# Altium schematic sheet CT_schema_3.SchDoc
size 321 x 302 mm
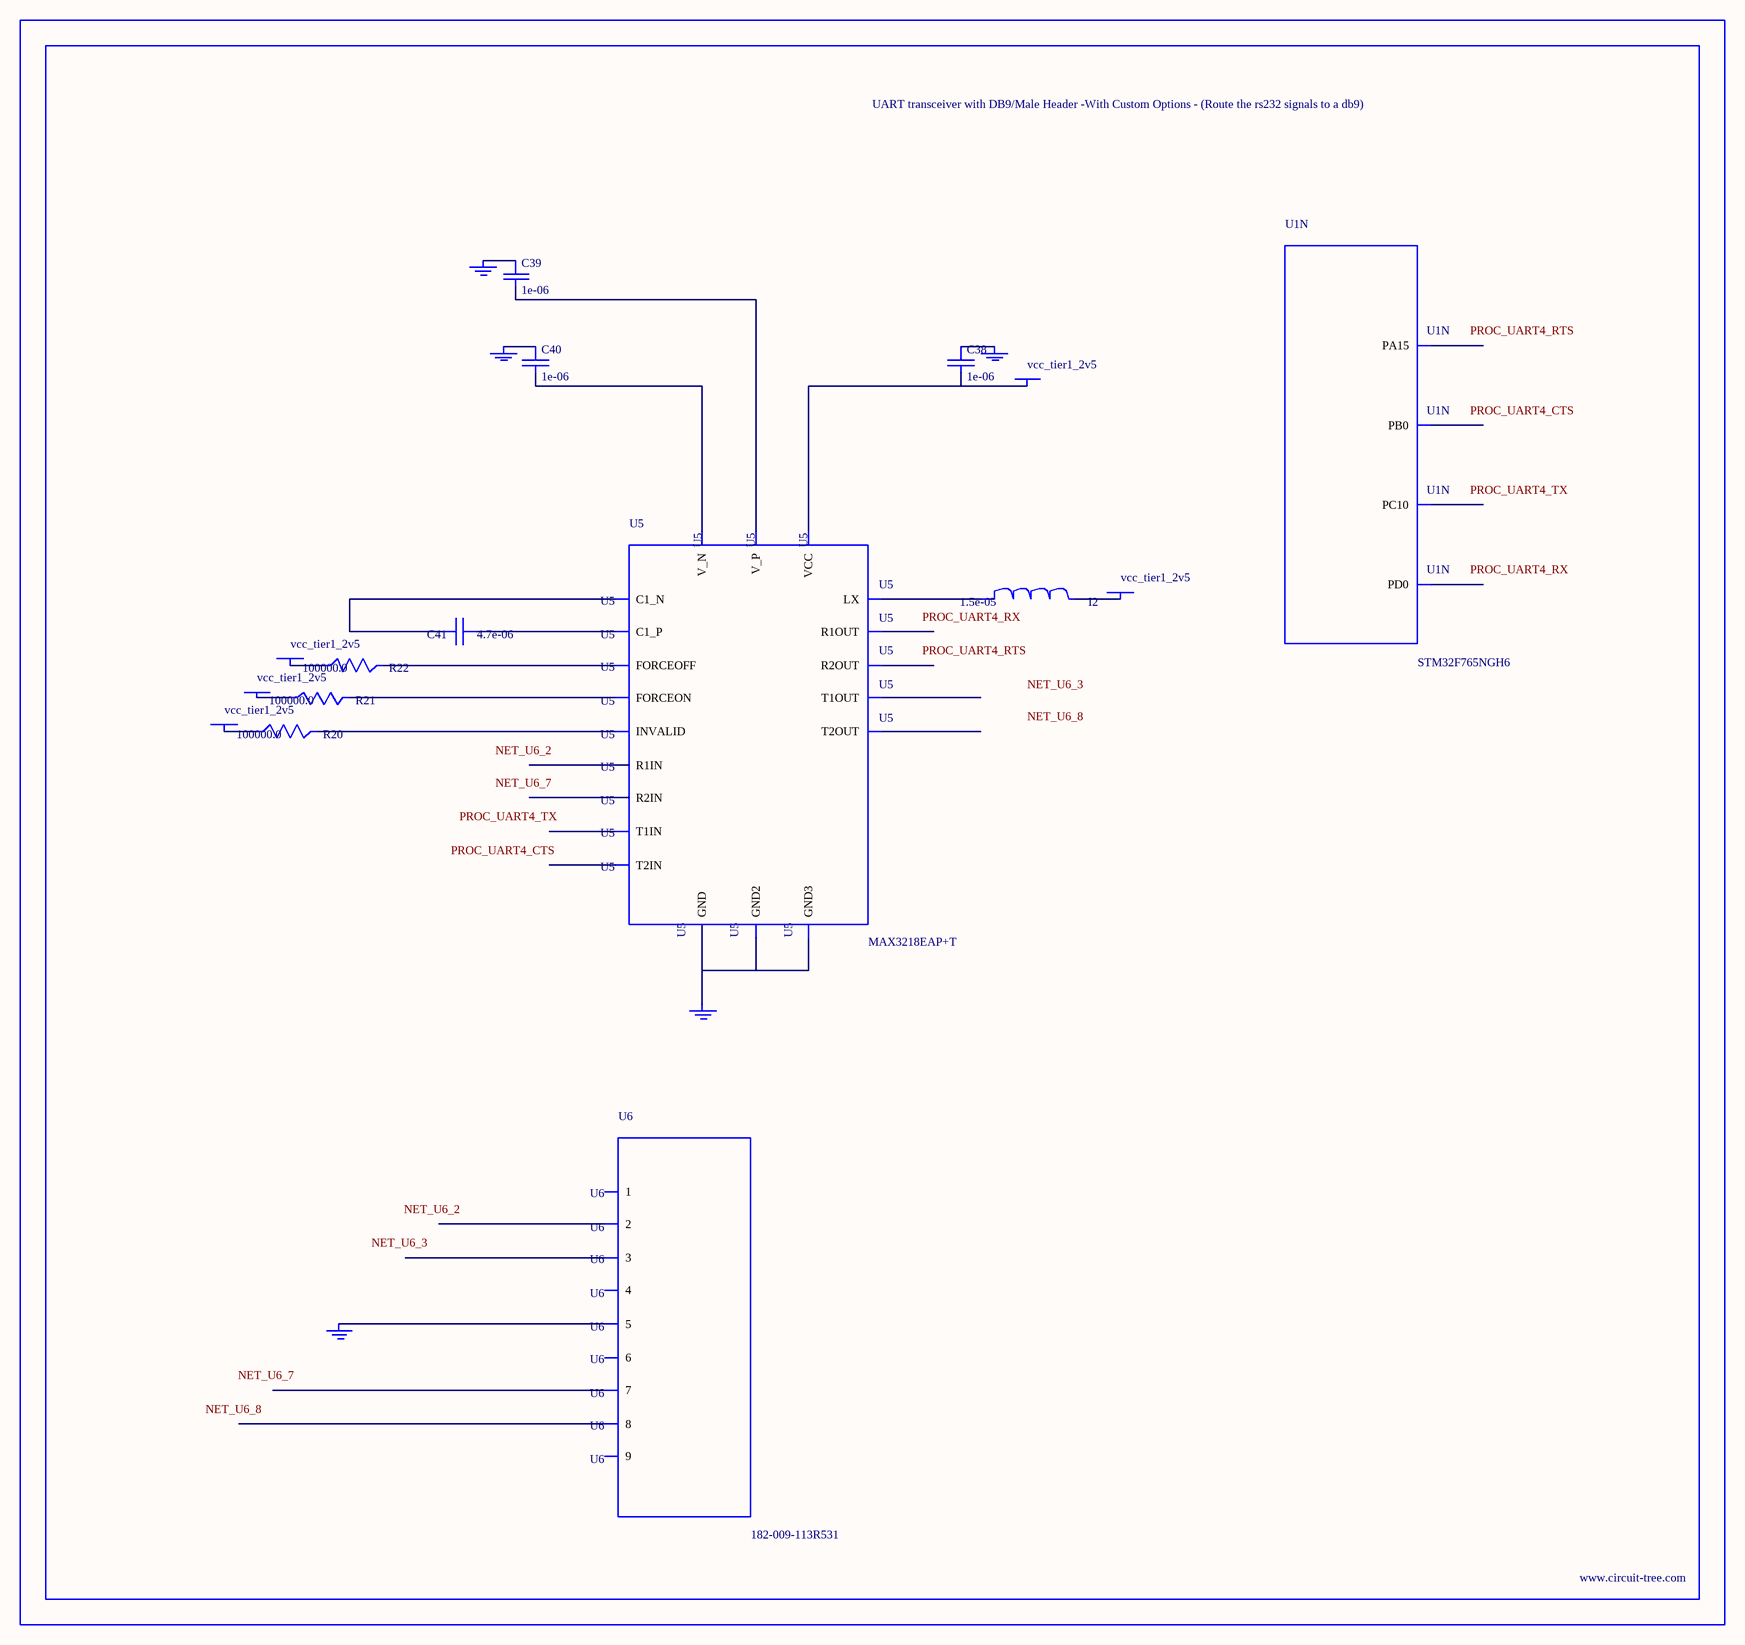
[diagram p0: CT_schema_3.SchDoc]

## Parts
BORDER2  (no value)
C38  1e-06  [C0603]
C39  1e-06  [C0603]
C40  1e-06  [C0603]
C41  4.7e-06  [C0805]
GND_INSTANCE_2_0  (no value)
GND_INSTANCE_2_1  (no value)
GND_INSTANCE_2_2  (no value)
GND_INSTANCE_2_3  (no value)
GND_INSTANCE_2_4  (no value)
I2  1.5e-05  [L1210]
POWER_INSTANCE_2_0  vcc_tier1_2v5
POWER_INSTANCE_2_1  vcc_tier1_2v5
POWER_INSTANCE_2_2  vcc_tier1_2v5
POWER_INSTANCE_2_3  vcc_tier1_2v5
POWER_INSTANCE_2_4  vcc_tier1_2v5
R20  100000.0  [R0603]
R21  100000.0  [R0603]
R22  100000.0  [R0603]
U1  STM32F765NGH6  [TFBGA216]  (part N of 18)
U5  MAX3218EAP+T  [SSOP-20]
U6  182-009-113R531  [182-009-MALE]

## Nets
NetC38_1: C38.1 GND_INSTANCE_2_0.0(GND)
NetC38_2: C38.2 POWER_INSTANCE_2_4.0(PWR) U5.6(VCC)
NetC39_1: C39.1 GND_INSTANCE_2_2.0(GND)
NetC39_2: C39.2 U5.19(V_P)
NetC40_1: C40.1 GND_INSTANCE_2_1.0(GND)
NetC40_2: C40.2 U5.15(V_N)
NetC41_1: C41.1 U5.18(C1_P)
NetC41_2: C41.2 U5.16(C1_N)
NetGND_INSTANCE_2_3_0: GND_INSTANCE_2_3.0(GND) U5.5(GND) U5.17(GND2) U5.20(GND3)
NetGND_INSTANCE_2_4_0: GND_INSTANCE_2_4.0(GND) U6.5
NetI2_1: I2.1 U5.1(LX)
NetI2_2: I2.2 POWER_INSTANCE_2_0.0(PWR)
NetPOWER_INSTANCE_2_1_0: POWER_INSTANCE_2_1.0(PWR) R20.1
NetPOWER_INSTANCE_2_2_0: POWER_INSTANCE_2_2.0(PWR) R21.1
NetPOWER_INSTANCE_2_3_0: POWER_INSTANCE_2_3.0(PWR) R22.1
NetR20_2: R20.2 U5.2(INVALID)
NetR21_2: R21.2 U5.3(FORCEON)
NetR22_2: R22.2 U5.4(FORCEOFF)

Not connected (* = marked no-connect by the designer): U1 A13(PA15) B12(PD0) B14(PC10) R5(PB0); U5 7(T1IN) 8(T2IN) 9(R1OUT) 10(R2OUT) 11(R2IN) 12(R1IN) 13(T2OUT) 14(T1OUT); U6 1 2 3 4 6 7 8 9

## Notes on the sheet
- Labels drawn without touching a wire or pin: NET_U6_2, NET_U6_3, NET_U6_7, NET_U6_8, PROC_UART4_CTS, PROC_UART4_RTS, PROC_UART4_RX, PROC_UART4_TX

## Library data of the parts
BORDER2 = BORDER_PAGE2
C38-C40 = C0603C105K3RACTU
C41 = C0805C475K4RACTU
GND_INSTANCE_2_0-GND_INSTANCE_2_4 = GND
I2 = L1210R150MDWIT
POWER_INSTANCE_2_0-POWER_INSTANCE_2_4 = PWR
R20-R22 = RC0603JR-07100KL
